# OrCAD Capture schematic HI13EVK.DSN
size A; title: HI13_EVK; rev: A1; note: 1
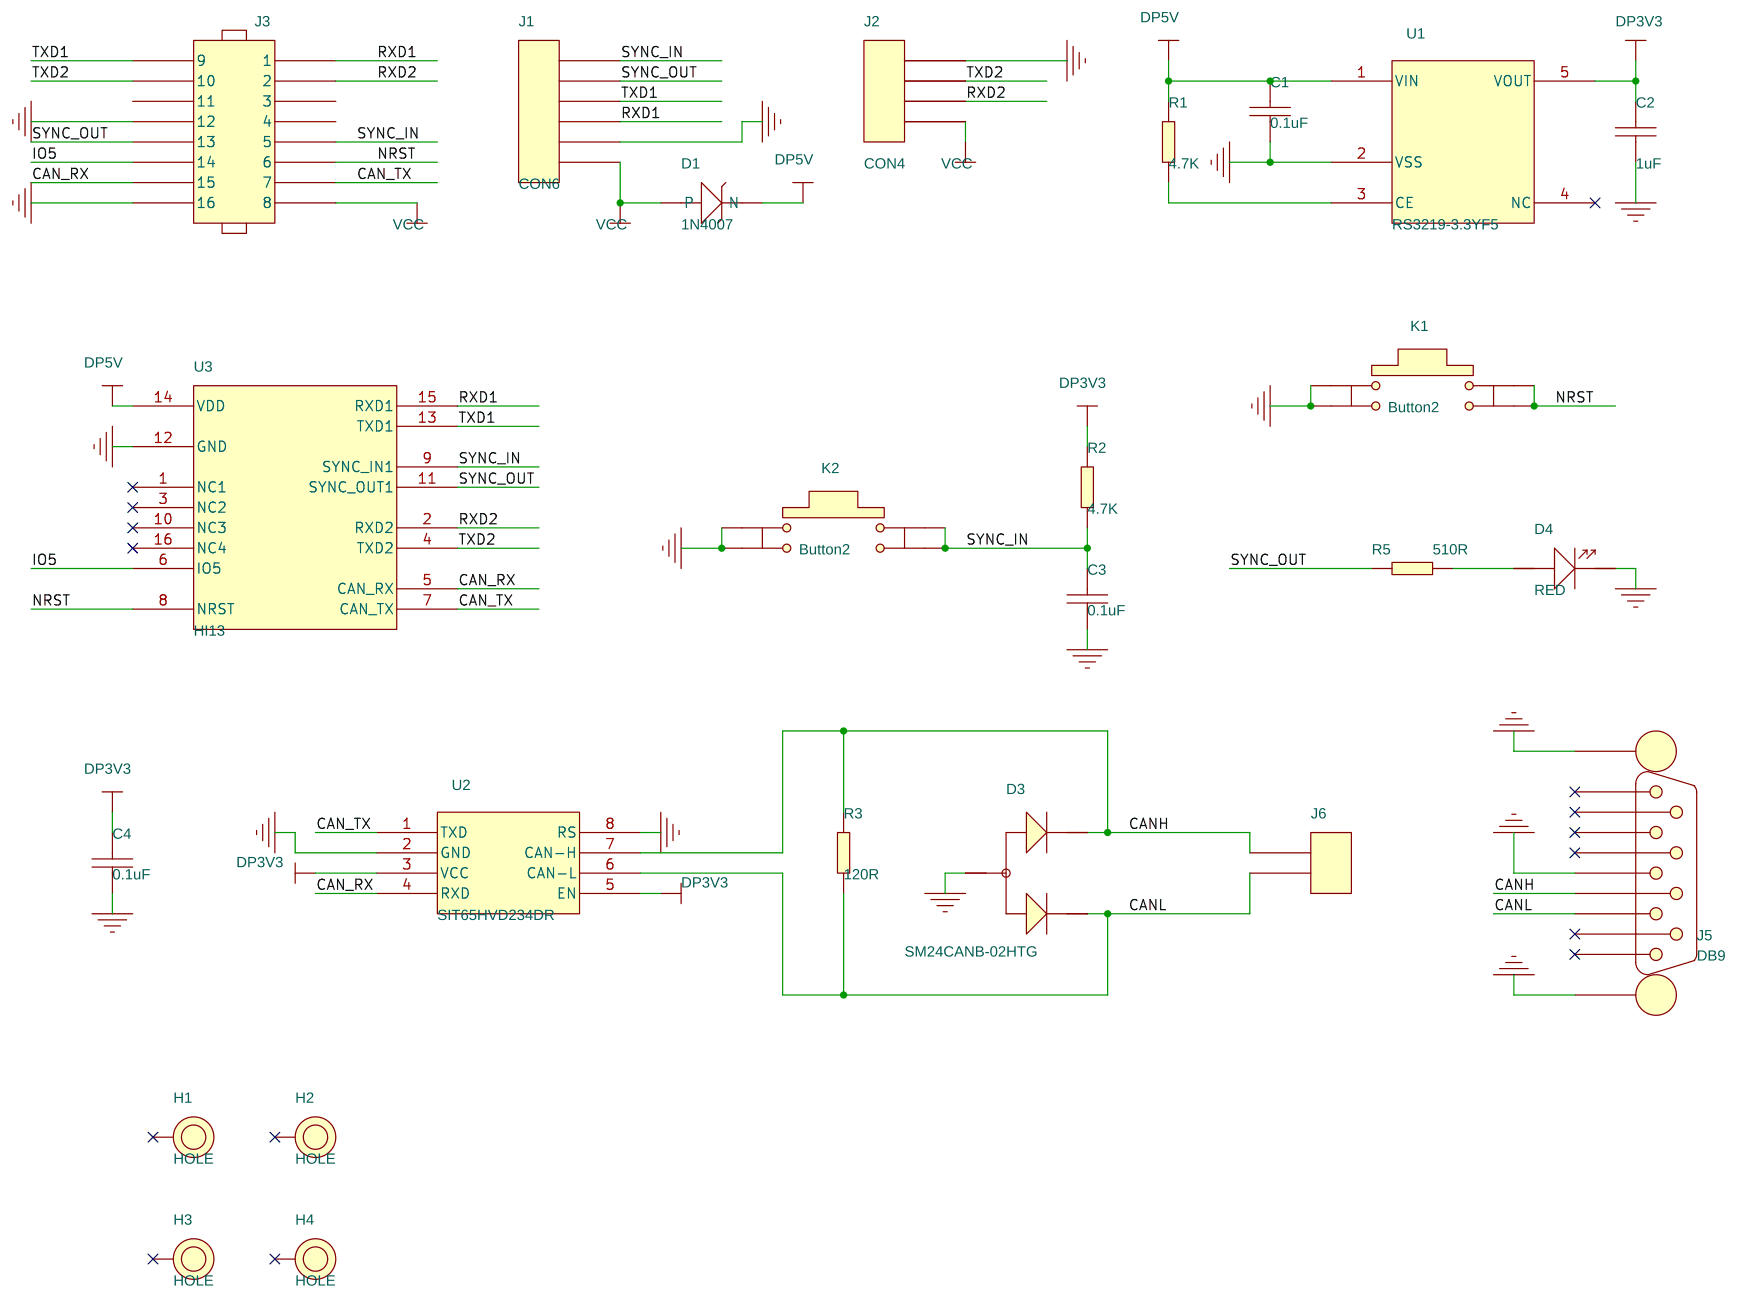
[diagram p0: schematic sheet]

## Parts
C1  0.1uF  [C0603]
C2  1uF  [C0603]
C3  0.1uF  [C0603]
C4  0.1uF  [C0603]
D1  1N4007  [DO-214AC]
D3  SM24CANB-02HTG  [SOT23-3-0_95]
D4  RED  [LED0603]
H1  HOLE  [HOLE-3-MM]
H2  HOLE  [HOLE-3-MM]
H3  HOLE  [HOLE-3-MM]
H4  HOLE  [HOLE-3-MM]
J1  CON6  [A1257WV-S-6P]
J2  CON4  [GH1X4-1_25mm_90]
J3  CONN PCB 8x2  [HEADER2X8-2_54mm]
J5  DB9  [DB9_Female]
J6  CONN PCB 2  [HEADER1X2-2_54mm]
K1  Button2  [BUTTON_6x6]
K2  Button2  [BUTTON_6x6]
R1  4.7K  [R0603]
R2  4.7K  [R0603]
R3  120R  [R1206]
R5  510R  [R0603]
U1  RS3219-3.3YF5  [SOT23-5-0_95]
U2  SIT65HVD234DR  [SOP8]
U3  HI13  [hi13_ucx]

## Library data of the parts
C1-C4 = Capacity_Nonpolarity
D1 = diode
D3 = BAT54A_SOT
D4 = LED
H1-H4 = HOLE
J1 = CON6
J2 = CON4
J3 = CONN_PCB_8x2
J5 = CONN_DB9M_MTGTABS: CON 9 DB MALE 0.318 PLUG RA SHLD TH 109MIL SP 500H -- 145L; AGILE_PN: 210-82038; CAD_APPROVED: Yes; HEIGHT: 12.7MM; MFG_NAME01: REGAL ELECTRONICS; MFG_PN01: R4019-09BT; Package Type: TH; ROHS: Yes; Temp Range: -55C to +105C; Temp_Range: -55C to +105C; VOLTAGE: 300V
J6 = CONN_PCB_2
K1 K2 = Button2
R1-R3 R5 = Res
U1 = XC6210
U2 = SN65HVD234-Q1
U3 = hi13

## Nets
GND: C1.2 C2.1 C3.1 C4.1 D3.3 D4.2(-) J1.2 J2.4 J3.7(12) J3.15(16) J5.3 J5.M1 J5.M2 K1.1 K1.2 K2.1 K2.2 U1.2(VSS) U2.2(GND) U2.8(RS) U3.12(GND)
VCC: D1.1(P) J1.1 J2.1 J3.16(8)
CAN_RX: J3.13(15) U2.4(RXD) U3.5(CAN_RX)
CAN_TX: J3.14(7) U2.1(TXD) U3.7(CAN_TX)
CANH: D3.1 J5.7 J6.1 R3.1 U2.7(CAN-H)
CANL: D3.2 J5.2 J6.2 R3.2 U2.6(CAN-L)
DP3V3: C2.2 C4.2 R2.2 U1.5(VOUT) U2.3(VCC) U2.5(EN)
DP5V: C1.1 D1.2(N) R1.2 U1.1(VIN) U3.14(VDD)
IO5: J3.11(14) U3.6(IO5)
NRST: J3.12(6) K1.3 K1.4 U3.8(NRST)
RXD1: J1.3 J3.2(1) U3.15(RXD1)
RXD2: J2.2 J3.4(2) U3.2(RXD2)
SYNC_IN: C3.2 J1.6 J3.10(5) K2.3 K2.4 R2.1 U3.9(SYNC_IN1)
SYNC_OUT: J1.5 J3.9(13) R5.1 U3.11(SYNC_OUT1)
TXD1: J1.4 J3.1(9) U3.13(TXD1)
TXD2: J2.3 J3.3(10) U3.4(TXD2)
N1746824: D4.1(+) R5.2
N1748528: R1.1 U1.3(CE)

Not connected (* = marked no-connect by the designer): H1 1*; H2 1*; H3 1*; H4 1*; J3 5(11) 6(3) 8(4); J5 1* 4* 5* 6* 8* 9*; U1 4(NC)*; U3 1(NC1)* 3(NC2)* 10(NC3)* 16(NC4)*
